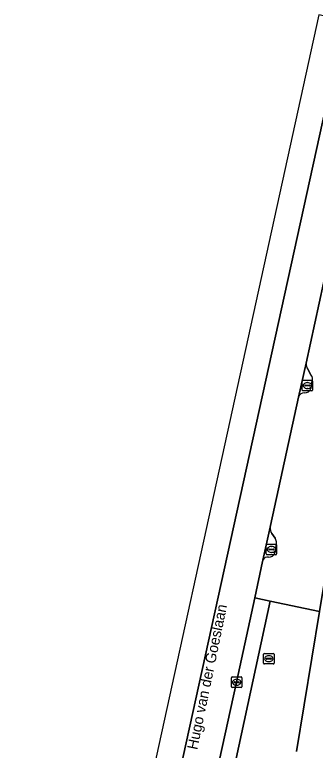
# Model space of a CAD drawing. Extents: x 163043 to 165076, y 382019 to 382874.
# Drawn here: x 163091.3 to 163119.9, y 382780.4 to 382850.6 of the extents above; entities that cross this region are included whole.
import ezdxf

# ---------------------------------------------------------------- set-up
doc = ezdxf.new("R2010")
doc.units = 0
for name, color, linetype in [('IMGEO_Berm_groen', 7, 'Continuous'), ('IMGEO_Berm_open', 7, 'Continuous'), ('IMGEO_Kolk', 7, 'Continuous'), ('IMGEO_Openbare_ruimte_label', 7, 'Continuous'), ('IMGEO_Rijbaan_regionaal_gesloten', 7, 'Continuous'), ('IMGEO_Rioolput', 7, 'Continuous')]:
    doc.layers.add(name, color=color, linetype=linetype)

msp = doc.modelspace()

# ---------------------------------------------------------------- linework, layer by layer
at = {"layer": 'IMGEO_Berm_groen'}
for points in [[(163121.136, 382826.919), (163119.07, 382817.368)], [(163119.239, 382816.767), (163119.528, 382816.236)], [(163119.618, 382815.547), (163119.527, 382814.918)], [(163118.339, 382814.111), (163115.672, 382801.834), (163115.64, 382801.69)], [(163114.939, 382798.525), (163114.915, 382798.417), (163114.168, 382794.935), (163115.63, 382794.599), (163120.341, 382793.612), (163123.418, 382812.236)], [(163123.418, 382812.236), (163120.341, 382793.612), (163118.136, 382780.262)], [(163115.795, 382801.082), (163116.104, 382800.649)], [(163116.224, 382799.902), (163116.092, 382799.223)], [(163118.136, 382780.262), (163120.341, 382793.612), (163115.63, 382794.599), (163108.285, 382760.577), (163100.666, 382724.498), (163102.091, 382725.758)]]:
    msp.add_lwpolyline(points, dxfattribs=at)
msp.add_lwpolyline([(163108.285, 382760.577), (163115.63, 382794.599), (163114.168, 382794.935), (163112.439, 382786.872), (163109.102, 382771.769), (163104.532, 382750), (163098.978, 382724.989), (163100.179, 382724.705), (163100.666, 382724.498)], close=True, dxfattribs=at)
for centre, radius, start, end in [((163119.884, 382817.273), 0.82, 173.3282, 218.08355), ((163119.134, 382815.834), 0.563, 329.33105, 45.55309), ((163118.929, 382815.151), 0.642, 270.03281, 338.70727), ((163118.867, 382813.964), 0.548, 83.52875, 164.47659), ((163116.478, 382801.58), 0.845, 172.50946, 216.09456), ((163115.231, 382800.126), 1.018, 347.30698, 30.94536), ((163115.379, 382798.372), 0.466, 78.24914, 160.8014), ((163115.527, 382799.426), 0.601, 264.94774, 340.22232)]:
    msp.add_arc(centre, radius, start, end, dxfattribs=at)
at = {"layer": 'IMGEO_Berm_open'}
for points in [[(163119.07, 382817.368), (163118.339, 382814.111)], [(163119.528, 382816.236), (163119.239, 382816.767)], [(163119.527, 382814.918), (163119.618, 382815.547)], [(163115.64, 382801.69), (163114.939, 382798.525)], [(163116.104, 382800.649), (163115.795, 382801.082)], [(163116.092, 382799.223), (163116.224, 382799.902)]]:
    msp.add_lwpolyline(points, dxfattribs=at)
for centre, radius, start, end in [((163119.884, 382817.273), 0.82, 173.3282, 218.08355), ((163119.134, 382815.834), 0.563, 329.33105, 45.55309), ((163118.929, 382815.151), 0.642, 270.03281, 338.70727), ((163118.867, 382813.964), 0.548, 83.52875, 164.47659), ((163116.478, 382801.58), 0.845, 172.50946, 216.09456), ((163115.231, 382800.126), 1.018, 347.30698, 30.94536), ((163115.379, 382798.372), 0.466, 78.24914, 160.8014), ((163115.527, 382799.426), 0.601, 264.94774, 340.22232)]:
    msp.add_arc(centre, radius, start, end, dxfattribs=at)
at = {"layer": 'IMGEO_Kolk'}
for p, q in [((163118.688, 382814.788), (163118.688, 382815.64)), ((163118.763, 382815.714), (163119.615, 382815.714)), ((163119.176, 382815.494), (163119.201, 382815.494)), ((163119.689, 382815.64), (163119.689, 382814.788)), ((163118.947, 382815.208), (163118.947, 382815.22)), ((163119.385, 382815.171), (163118.987, 382815.171)), ((163118.99, 382815.257), (163119.388, 382815.257)), ((163119.199, 382814.934), (163119.174, 382814.934)), ((163119.431, 382815.22), (163119.431, 382815.208)), ((163119.615, 382814.714), (163118.763, 382814.714)), ((163115.328, 382800.055), (163116.18, 382800.055)), ((163115.253, 382799.129), (163115.253, 382799.981)), ((163115.512, 382799.549), (163115.512, 382799.561)), ((163115.95, 382799.512), (163115.552, 382799.512)), ((163115.555, 382799.598), (163115.953, 382799.598)), ((163115.741, 382799.835), (163115.766, 382799.835)), ((163115.996, 382799.561), (163115.996, 382799.549)), ((163116.254, 382799.981), (163116.254, 382799.129)), ((163116.18, 382799.055), (163115.328, 382799.055)), ((163115.764, 382799.275), (163115.739, 382799.275)), ((163112.014, 382787.371), (163112.866, 382787.371)), ((163111.939, 382786.445), (163111.939, 382787.297)), ((163112.198, 382786.865), (163112.198, 382786.877)), ((163112.636, 382786.828), (163112.238, 382786.828)), ((163112.241, 382786.914), (163112.639, 382786.914)), ((163112.427, 382787.151), (163112.452, 382787.151)), ((163112.682, 382786.877), (163112.682, 382786.865)), ((163112.94, 382787.297), (163112.94, 382786.445)), ((163112.866, 382786.371), (163112.014, 382786.371)), ((163112.45, 382786.591), (163112.425, 382786.591))]:
    msp.add_line(p, q, dxfattribs=at)
for points in [[(163118.688, 382814.788), (163118.688, 382815.64)], [(163118.763, 382815.714), (163119.615, 382815.714)], [(163119.689, 382815.64), (163119.689, 382814.788)], [(163119.615, 382814.714), (163118.763, 382814.714)], [(163115.328, 382800.055), (163116.18, 382800.055)], [(163115.253, 382799.129), (163115.253, 382799.981)], [(163116.254, 382799.981), (163116.254, 382799.129)], [(163116.18, 382799.055), (163115.328, 382799.055)], [(163112.014, 382787.371), (163112.866, 382787.371)], [(163111.939, 382786.445), (163111.939, 382787.297)], [(163112.94, 382787.297), (163112.94, 382786.445)], [(163112.866, 382786.371), (163112.014, 382786.371)]]:
    msp.add_lwpolyline(points, dxfattribs=at)
for centre, radius, start, end in [((163118.765, 382815.638), 0.0765, 91.55205, 178.44795), ((163118.765, 382815.638), 0.0765, 91.55205, 178.44795), ((163119.613, 382815.638), 0.0765, 1.55205, 88.44795), ((163119.613, 382815.638), 0.0765, 1.55205, 88.44795), ((163118.765, 382814.79), 0.0765, 181.55205, 268.44795), ((163118.765, 382814.79), 0.0765, 181.55205, 268.44795), ((163118.987, 382815.217), 0.0403, 85.87752, 175.75265), ((163118.984, 382815.207), 0.0366, 178.93798, 274.71019), ((163119.388, 382815.214), 0.043, 264.86636, 352.45326), ((163119.392, 382815.219), 0.0386, 1.73085, 96.63898), ((163119.613, 382814.79), 0.0765, 271.55205, 358.44795), ((163119.613, 382814.79), 0.0765, 271.55205, 358.44795), ((163115.33, 382799.979), 0.0765, 91.55205, 178.44795), ((163115.33, 382799.979), 0.0765, 91.55205, 178.44795), ((163116.178, 382799.979), 0.0765, 1.55205, 88.44795), ((163116.178, 382799.979), 0.0765, 1.55205, 88.44795), ((163115.552, 382799.558), 0.0403, 85.87752, 175.75265), ((163115.549, 382799.548), 0.0366, 178.93798, 274.71019), ((163115.953, 382799.555), 0.043, 264.86636, 352.45326), ((163115.957, 382799.56), 0.0386, 1.73085, 96.63898), ((163115.33, 382799.131), 0.0765, 181.55205, 268.44795), ((163115.33, 382799.131), 0.0765, 181.55205, 268.44795), ((163116.178, 382799.131), 0.0765, 271.55205, 358.44795), ((163116.178, 382799.131), 0.0765, 271.55205, 358.44795), ((163112.016, 382787.295), 0.0765, 91.55205, 178.44795), ((163112.016, 382787.295), 0.0765, 91.55205, 178.44795), ((163112.864, 382787.295), 0.0765, 1.55205, 88.44795), ((163112.864, 382787.295), 0.0765, 1.55205, 88.44795), ((163112.238, 382786.874), 0.0403, 85.87752, 175.75265), ((163112.235, 382786.864), 0.0366, 178.93798, 274.71019), ((163112.639, 382786.871), 0.043, 264.86636, 352.45326), ((163112.643, 382786.876), 0.0386, 1.73085, 96.63898), ((163112.016, 382786.447), 0.0765, 181.55205, 268.44795), ((163112.016, 382786.447), 0.0765, 181.55205, 268.44795), ((163112.864, 382786.447), 0.0765, 271.55205, 358.44795), ((163112.864, 382786.447), 0.0765, 271.55205, 358.44795)]:
    msp.add_arc(centre, radius, start, end, dxfattribs=at)
for centre, major_axis, ratio, start_param, end_param in [((163119.175, 382815.214), (-0.387, 0.002), 0.722429, 4.712389, 7.853982), ((163119.2, 382815.214), (-0.39, 0.002), 0.717154, 1.570796, 4.712389), ((163115.74, 382799.555), (-0.387, 0.002), 0.722429, 4.712389, 7.853982), ((163115.765, 382799.555), (-0.39, 0.002), 0.717154, 1.570796, 4.712389), ((163112.426, 382786.871), (-0.387, 0.002), 0.722429, 4.712389, 7.853982), ((163112.451, 382786.871), (-0.39, 0.002), 0.717154, 1.570796, 4.712389)]:
    msp.add_ellipse(centre, major_axis=major_axis, ratio=ratio, start_param=start_param, end_param=end_param, dxfattribs=at)
at = {"layer": 'IMGEO_Rijbaan_regionaal_gesloten'}
msp.add_lwpolyline([(163091.253, 382717.588), (163093.262, 382717.136), (163093.637, 382717.052), (163099.919, 382746.137), (163106.108, 382774.281), (163122.779, 382850.09), (163120.278, 382850.642), (163095.999, 382739.744)], close=True, dxfattribs=at)
for points in [[(163124.485, 382838.969), (163125.405, 382841.379), (163125.839, 382842.316), (163127.104, 382848.167), (163127.308, 382849.09), (163123.339, 382849.966), (163122.779, 382850.09), (163106.108, 382774.281), (163099.919, 382746.137), (163093.637, 382717.052), (163097.045, 382716.284), (163097.286, 382717.37), (163098.978, 382724.989), (163104.532, 382750), (163109.102, 382771.769), (163112.439, 382786.872)], [(163112.439, 382786.872), (163114.168, 382794.935), (163114.915, 382798.417), (163114.939, 382798.525), (163115.64, 382801.69), (163115.672, 382801.834), (163118.339, 382814.111), (163119.07, 382817.368), (163121.136, 382826.919), (163121.89, 382830.225), (163122.542, 382833.239)]]:
    msp.add_lwpolyline(points, dxfattribs=at)
at = {"layer": 'IMGEO_Rioolput'}
for p, q in [((163115.01, 382788.69), (163115.01, 382789.542)), ((163115.085, 382789.616), (163115.937, 382789.616)), ((163116.011, 382789.542), (163116.011, 382788.69)), ((163115.269, 382789.11), (163115.269, 382789.122)), ((163115.707, 382789.073), (163115.309, 382789.073)), ((163115.312, 382789.159), (163115.71, 382789.159)), ((163115.521, 382788.836), (163115.496, 382788.836)), ((163115.498, 382789.396), (163115.523, 382789.396)), ((163115.753, 382789.122), (163115.753, 382789.11)), ((163115.937, 382788.616), (163115.085, 382788.616))]:
    msp.add_line(p, q, dxfattribs=at)
for points in [[(163115.01, 382788.69), (163115.01, 382789.542)], [(163115.085, 382789.616), (163115.937, 382789.616)], [(163116.011, 382789.542), (163116.011, 382788.69)], [(163115.937, 382788.616), (163115.085, 382788.616)]]:
    msp.add_lwpolyline(points, dxfattribs=at)
for centre, radius, start, end in [((163115.087, 382789.54), 0.0765, 91.55205, 178.44795), ((163115.087, 382789.54), 0.0765, 91.55205, 178.44795), ((163115.935, 382789.54), 0.0765, 1.55205, 88.44795), ((163115.935, 382789.54), 0.0765, 1.55205, 88.44795), ((163115.309, 382789.119), 0.0403, 85.87752, 175.75265), ((163115.306, 382789.109), 0.0366, 178.93798, 274.71019), ((163115.71, 382789.116), 0.043, 264.86636, 352.45326), ((163115.714, 382789.121), 0.0386, 1.73085, 96.63898), ((163115.087, 382788.692), 0.0765, 181.55205, 268.44795), ((163115.087, 382788.692), 0.0765, 181.55205, 268.44795), ((163115.935, 382788.692), 0.0765, 271.55205, 358.44795), ((163115.935, 382788.692), 0.0765, 271.55205, 358.44795)]:
    msp.add_arc(centre, radius, start, end, dxfattribs=at)
for centre, major_axis, ratio, start_param, end_param in [((163115.497, 382789.116), (-0.387, 0.002), 0.722429, 4.712389, 7.853982), ((163115.522, 382789.116), (-0.39, 0.002), 0.717154, 1.570796, 4.712389)]:
    msp.add_ellipse(centre, major_axis=major_axis, ratio=ratio, start_param=start_param, end_param=end_param, dxfattribs=at)

# ---------------------------------------------------------------- texts
at = {"layer": 'IMGEO_Openbare_ruimte_label'}
msp.add_text('Hugo van der Goeslaan', height=1, rotation=78.3416, dxfattribs=at).set_placement((163108.678, 382780.367))

doc.saveas('drawing.dxf')
